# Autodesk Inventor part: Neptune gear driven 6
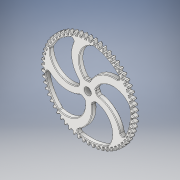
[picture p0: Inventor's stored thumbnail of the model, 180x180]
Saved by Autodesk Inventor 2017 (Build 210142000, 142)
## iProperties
Created: 2016-05
Part Number: Neptune gear driven 6
Material: Generic
Document SubType Name: Modeling
Designer: Stan
Density: 1 g/cm^3
Appearance: White
Author: Stan
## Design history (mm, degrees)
sketch "Sketch1"
  geometry: A1 r 20.278 centre (-28.447, 51.558) between (-10.472, 60.945) and (-12.828, 64.491); A2 r 20.278 centre (-28.447, 51.558) between (-10.472, 60.945) and (-12.828, 64.491); A3 r 20.278 centre (11.122, 57.825) between (-7.729, 65.298) and (-8.873, 61.198); A4 r 20.278 centre (11.122, 57.825) between (-7.729, 65.298) and (-8.873, 61.198); A5 r 20.278 centre (-33.68, 48.302) between (-16.785, 59.517) and (-19.499, 62.796); A6 r 20.278 centre (-33.68, 48.302) between (-16.785, 59.517) and (-19.499, 62.796); A7 r 20.278 centre (5.017, 58.671) between (-14.512, 64.133) and (-15.222, 59.935); A8 r 20.278 centre (5.017, 58.671) between (-14.512, 64.133) and (-15.222, 59.935); A9 r 20.278 centre (-38.545, 44.517) between (-22.915, 57.436) and (-25.956, 60.414); A10 r 20.278 centre (-38.545, 44.517) between (-22.915, 57.436) and (-25.956, 60.414); A11 r 20.278 centre (-1.143, 58.874) between (-21.136, 62.264) and (-21.403, 58.016); A12 r 20.278 centre (-1.143, 58.874) between (-21.136, 62.264) and (-21.403, 58.016); A13 r 20.278 centre (-42.987, 40.244) between (-28.793, 54.726) and (-32.129, 57.37); A14 r 20.278 centre (-42.987, 40.244) between (-28.793, 54.726) and (-32.129, 57.37); A15 r 20.278 centre (-7.291, 58.432) between (-27.529, 59.714) and (-27.35, 55.461); A16 r 20.278 centre (-7.291, 58.432) between (-27.529, 59.714) and (-27.35, 55.461); A17 r 20.278 centre (-46.958, 35.53) between (-34.355, 51.417) and (-37.95, 53.697); A18 r 20.278 centre (-46.958, 35.53) between (-34.355, 51.417) and (-37.95, 53.697); A19 r 20.278 centre (-13.359, 57.35) between (-33.62, 56.509) and (-32.998, 52.298); A20 r 20.278 centre (-13.359, 57.35) between (-33.62, 56.509) and (-32.998, 52.298); A21 r 20.278 centre (-50.415, 30.427) between (-39.542, 47.544) and (-43.355, 49.437); A22 r 20.278 centre (-50.415, 30.427) between (-39.542, 47.544) and (-43.355, 49.437); A23 r 20.278 centre (-19.28, 55.639) between (-39.342, 52.686) and (-38.284, 48.563); A24 r 20.278 centre (-19.28, 55.639) between (-39.342, 52.686) and (-38.284, 48.563); A25 r 20.278 centre (-53.319, 24.991) between (-44.295, 43.15) and (-48.285, 44.634); A26 r 20.278 centre (-53.319, 24.991) between (-44.295, 43.15) and (-48.285, 44.634); A27 r 20.278 centre (-24.991, 53.319) between (-44.634, 48.285) and (-43.15, 44.295); A28 r 20.278 centre (-24.991, 53.319) between (-44.634, 48.285) and (-43.15, 44.295); A29 r 20.278 centre (-55.639, 19.28) between (-48.563, 38.284) and (-52.686, 39.342); A30 r 20.278 centre (-55.639, 19.28) between (-48.563, 38.284) and (-52.686, 39.342); A31 r 20.278 centre (-30.427, 50.415) between (-49.437, 43.355) and (-47.544, 39.542); A32 r 20.278 centre (-30.427, 50.415) between (-49.437, 43.355) and (-47.544, 39.542); A33 r 20.278 centre (-57.35, 13.359) between (-52.298, 32.998) and (-56.509, 33.62); A34 r 20.278 centre (-57.35, 13.359) between (-52.298, 32.998) and (-56.509, 33.62); A35 r 20.278 centre (-35.53, 46.958) between (-53.697, 37.95) and (-51.417, 34.355); A36 r 20.278 centre (-35.53, 46.958) between (-53.697, 37.95) and (-51.417, 34.355); A37 r 20.278 centre (-58.432, 7.291) between (-55.461, 27.35) and (-59.714, 27.529); A38 r 20.278 centre (-58.432, 7.291) between (-55.461, 27.35) and (-59.714, 27.529); A39 r 20.278 centre (-40.244, 42.987) between (-57.37, 32.129) and (-54.726, 28.793); A40 r 20.278 centre (-40.244, 42.987) between (-57.37, 32.129) and (-54.726, 28.793); A41 r 20.278 centre (-58.874, 1.143) between (-58.016, 21.403) and (-62.264, 21.136); A42 r 20.278 centre (-58.874, 1.143) between (-58.016, 21.403) and (-62.264, 21.136); A43 r 20.278 centre (-44.517, 38.545) between (-60.414, 25.956) and (-57.436, 22.915); A44 r 20.278 centre (-44.517, 38.545) between (-60.414, 25.956) and (-57.436, 22.915); A45 r 20.278 centre (-58.671, -5.017) between (-59.935, 15.222) and (-64.133, 14.512); A46 r 20.278 centre (-58.671, -5.017) between (-59.935, 15.222) and (-64.133, 14.512); A47 r 20.278 centre (-48.302, 33.68) between (-62.796, 19.499) and (-59.517, 16.785); A48 r 20.278 centre (-48.302, 33.68) between (-62.796, 19.499) and (-59.517, 16.785); A49 r 20.278 centre (-57.825, -11.122) between (-61.198, 8.873) and (-65.298, 7.729); A50 r 20.278 centre (-57.825, -11.122) between (-61.198, 8.873) and (-65.298, 7.729); A51 r 20.278 centre (-51.558, 28.447) between (-64.491, 12.828) and (-60.945, 10.472); A52 r 20.278 centre (-51.558, 28.447) between (-64.491, 12.828) and (-60.945, 10.472); A53 r 20.278 centre (-56.346, -17.106) between (-61.791, 2.428) and (-65.748, 0.861); A54 r 20.278 centre (-56.346, -17.106) between (-61.791, 2.428) and (-65.748, 0.861); A55 r 20.278 centre (-54.249, 22.902) between (-65.478, 6.017) and (-61.706, 4.044); A56 r 20.278 centre (-54.249, 22.902) between (-65.478, 6.017) and (-61.706, 4.044); A57 r 20.278 centre (-54.249, -22.902) between (-61.706, -4.044) and (-65.478, -6.017); A58 r 20.278 centre (-54.249, -22.902) between (-61.706, -4.044) and (-65.478, -6.017); A59 r 20.278 centre (-56.346, 17.106) between (-65.748, -0.861) and (-61.791, -2.428); A60 r 20.278 centre (-56.346, 17.106) between (-65.748, -0.861) and (-61.791, -2.428); A61 r 20.278 centre (-51.558, -28.447) between (-60.945, -10.472) and (-64.491, -12.828); A62 r 20.278 centre (-51.558, -28.447) between (-60.945, -10.472) and (-64.491, -12.828); A63 r 20.278 centre (-57.825, 11.122) between (-65.298, -7.729) and (-61.198, -8.873); A64 r 20.278 centre (-57.825, 11.122) between (-65.298, -7.729) and (-61.198, -8.873)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; 1 further point
  constraints: 960 point on circle, 480 centre point, 8 horizontal alignment, 8 vertical alignment, 1424 other
extrude "Extrusion1" new body sketch "Sketch1" distance "d0" = 6.35; taper "d1" = 0 deg
sketch "Sketch2"
  geometry: A1 r 59.266 centre (0, 0) between (46.344, -36.942) and (58.233, 11.018); A2 r 59.266 centre (0, 0) between (49.455, 32.66) and (7.516, 58.788); A3 r 59.266 centre (0, 0) between (-15.779, 57.127) and (-53.588, 25.314); A4 r 59.266 centre (0, 0) between (-59.207, 2.646) and (-40.635, -43.142); A5 r 59.266 centre (0, 0) between (-20.813, -55.491) and (28.474, -51.978); A6 r 37.574 centre (14.018, 34.237) between (-15.779, 57.127) and (-11.055, 6.252); A7 r 27.6 centre (15.15, 32.264) between (7.516, 58.788) and (-3.736, 12.138); A8 r 37.574 centre (-28.229, 23.912) between (-59.207, 2.646) and (-9.362, -8.582); A9 r 27.6 centre (-26.003, 24.379) between (-53.588, 25.314) and (-12.698, 0.197); A10 r 37.574 centre (-31.465, -19.459) between (-20.813, -55.491) and (5.269, -11.555); A11 r 27.6 centre (-31.221, -17.197) between (-40.635, -43.142) and (-4.112, -12.016); A12 r 37.574 centre (8.783, -35.938) between (46.344, -36.942) and (12.618, 1.44); A13 r 27.6 centre (6.708, -35.008) between (28.474, -51.978) and (10.157, -7.624); A14 r 37.574 centre (36.893, -2.752) between (49.455, 32.66) and (2.53, 12.446); A15 r 27.6 centre (35.367, -4.439) between (58.233, 11.018) and (10.389, 7.304); A16 r 12.7 centre (0, 0) between (-9.362, -8.582) and (-4.112, -12.016); A17 r 12.7 centre (0, 0) between (5.269, -11.555) and (10.157, -7.624); A18 r 12.7 centre (0, 0) between (12.618, 1.44) and (10.389, 7.304); A19 r 12.7 centre (0, 0) between (2.53, 12.446) and (-3.736, 12.138); A20 r 12.7 centre (0, 0) between (-11.055, 6.252) and (-12.698, 0.197); 1 further point
  constraints: 40 point on circle, 20 centre point
extrude "Extrusion2" cut sketch "Sketch2" distance "d2" = 6.35; taper "d3" = 0 deg
sketch "Sketch3"
  geometry: C1 r 5.159 at (0, 0); 1 further point
  constraints: 1 centre point, 1 coincident
  dimensions: "d4" = 10.31875 diameter of C1
extrude "Extrusion3" cut sketch "Sketch3" distance "d5" = 6.35; taper "d6" = 0 deg
fillet "Fillet1" dims "d7" = 3.175
fillet "Fillet2" dims "d8" = 3.175
fillet "Fillet3" dims "d9" = 0.79375
fillet "Fillet4" dims "d10" = 0.79375
fillet "Fillet5" dims "d11" = 0.79375
fillet "Fillet6" dims "d12" = 0.79375
fillet "Fillet7" dims "d13" = 0.79375
fillet "Fillet8" dims "d14" = 0.79375
fillet "Fillet9" dims "d15" = 0.79375
fillet "Fillet10" dims "d16" = 0.79375
body "Solid1"
